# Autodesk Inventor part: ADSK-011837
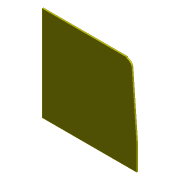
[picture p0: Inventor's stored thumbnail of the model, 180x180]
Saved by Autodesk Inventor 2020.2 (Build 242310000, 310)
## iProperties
Created: 1999-11
Part Number: ADSK-011837
Document SubType Name: Modeling
Designer: sspink
Material: Générique
Density: 1 g/cm^3
Appearance: Gelb
Mass: 142.564 g
Surface Area: 976.365 cm^2
Volume: 142.564 cm^3
Control State: 0
Checked Out: False
Last Check In By: sspink
Last Check In Date: 1999-12-22
Master: False
Shininess: 0.0
Length Units: 11269
Angle Units: 11279
Time Units: 11290
Mass Units: 11283
Length Display Precision: 3
Angle Display Precision: 2
Compacted: True
Dimensions: 220,5x3x220,5 mm
Mass: 0,143 kg
VLT_Material: Generisch
Density: 0.0
Volumn: 0.0
Area: 0.0
PropertySet Name: Model Information
Author: sspink
Revision Number: -
Title: ADSK-011837
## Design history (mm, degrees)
node "Solide1"
  node "Extrusion1" dims "d4" = 3, "d5" = 0
sketch "Sketch1"
  geometry: L1 (-29.73, -178.195)-(190.77, -178.195) reference; L2 (190.77, -178.195)-(190.77, -124.195); L3 (190.77, -124.195)-(178.27, 42.305); L4 (178.27, 42.305)-(-29.73, 42.305); L5 (-29.73, 42.305)-(-29.73, -178.195) reference; A1 r 3 centre (169.77, 42.305) between (166.77, 42.305) and (169.211, 39.358); A2 r 12.5 centre (166.878, 27.077) between (179.343, 28.013) and (169.211, 39.358)
  constraints: 10 end point, 4 point on circle, 3 point on line, 2 centre point, 2 horizontal, 2 parallel, 2 tangent, 1 perpendicular, 1 vertical
  dimensions: "d0" = 220.5 distance of L4.end L1.start; "d1" = 208 distance of L3.end L4.end (computed from d2); "d2" = 220.5 distance of L1.start L1.end; "d3" = 54 distance of L1.end L2.end; "d8" = 6 diameter of A1; "d10" = 8.5 distance of A1.centre L3.end; "d11" = 12.5 radius of A2
node "Corps solides"
node "Corps surfaciques"
